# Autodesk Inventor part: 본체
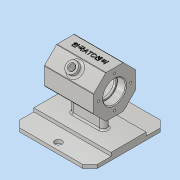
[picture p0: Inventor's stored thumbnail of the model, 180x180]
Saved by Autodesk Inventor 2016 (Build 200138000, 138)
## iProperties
Created: 2018-06
Part Number: 본체
Material: 알루미늄 6061
Document SubType Name: Modeling
Designer: Administrator
Density: 2.7 g/cm^3
Appearance: 알루미늄 - 평지
Mass: 551.991 g
Surface Area: 601.93 cm^2
Volume: 204.441 cm^3
Author: Administrator
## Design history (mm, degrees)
sketch "스케치1"
  geometry: L1 (30, -12.426)-(12.426, -30); L2 (12.426, -30)-(-12.426, -30); L3 (-12.426, -30)-(-30, -12.426); L4 (-30, -12.426)-(-30, 12.426); L5 (-30, 12.426)-(-12.426, 30); L6 (-12.426, 30)-(12.426, 30); L7 (12.426, 30)-(30, 12.426); L8 (30, 12.426)-(30, -12.426); 4 further points
  constraints: 16 end point, 2 coincident, 2 midpoint, 1 horizontal alignment, 1 vertical alignment, 17 other
  dimensions: "d0" = 30 distance of point (30, 0) point (0, 0)
extrude "돌출1" new body sketch "스케치1" stored distance "d1" = 70; taper "d2" = 0 deg
sketch "스케치2"
  geometry: L1 (16, -35)-(16, -23); L2 (16, -23)-(14, -23); L3 (14, -23)-(14, -20); L4 (14, -20)-(25, -20); L5 (25, -20)-(25, 20); L6 (25, 20)-(14, 20); L7 (14, 20)-(14, 23); L8 (14, 23)-(16, 23); L9 (16, 23)-(16, 35); L10 (16, 35)-(0, 35); L11 (0, -35)-(16, -35); 2 further points
  constraints: 22 end point, 8 perpendicular, 2 coincident, 2 horizontal, 2 point on line, 1 vertical, 4 other
  dimensions: "d3" = 70 distance of L10.end L11.start; "d4" = 32 dimension on L1.start; "d5" = 28 dimension on L2.end; "d6" = 50 dimension on L4.end; "d7" = 32 dimension on L8.end; "d8" = 12 distance of L8.end L9.end; "d9" = 40 distance of L4.end L5.end; "d10" = 12 distance of L1.start L1.end; "d11" = 3 distance of L2.end L3.end
revolve "회전1" sketch "스케치2" stored, may be unused: angle "d12" = 90 deg
node "작업 평면1"
sketch "스케치3"
  geometry: L1 (55, 55)-(-55, 55); L2 (-55, 55)-(-55, -55); L3 (-55, -55)-(55, -55); L4 (55, -55)-(55, 55); 3 further points
  constraints: 8 end point, 2 midpoint, 2 parallel, 1 horizontal, 1 horizontal alignment, 1 perpendicular, 1 vertical alignment
  dimensions: "d14" = 110 distance of L3.end L1.start; "d15" = 110 distance of L2.end L3.end
extrude "돌출2" join sketch "스케치3" distance "d16" = 5; taper "d17" = 0 deg
sketch "스케치4"
  geometry: L1 (-25, -55)-(25, -55); L2 (25, -55)-(25, 55); L3 (25, 55)-(-25, 55); L4 (-25, 55)-(-25, -55); 3 further points
  constraints: 8 end point, 2 midpoint, 2 parallel, 1 horizontal, 1 horizontal alignment, 1 perpendicular, 1 vertical alignment
  dimensions: "d18" = 110 distance of L3.end L1.start; "d19" = 50 distance of L2.end L3.end
extrude "돌출3" join sketch "스케치4" distance "d20" = 5; taper "d21" = 0 deg
sketch "스케치5"
  geometry: L1 (-5, -19)-(-5, 19); L2 (5, 19)-(5, -19); A1 r 5 centre (0, 19) between (5, 19) and (-5, 19); A2 r 5 centre (0, -19) between (-5, -19) and (5, -19); 2 further points
  constraints: 4 end point, 4 point on circle, 4 tangent, 2 centre point, 1 horizontal alignment, 1 midpoint, 1 parallel, 1 vertical, 1 vertical alignment
  dimensions: "d22" = 38 distance of L1.start L1.end; "d23" = 5 radius of A1
extrude "돌출4" join sketch "스케치5" stored distance "d24" = 5; taper "d25" = 0 deg
sketch "스케치6"
  geometry: C1 r 8 at (-12.426, 35); 1 further point
  constraints: 1 centre point, 1 coincident
  dimensions: "d26" = 16 diameter of C1
extrude "돌출5" join sketch "스케치6" distance "d27" = 7; taper "d28" = 0 deg
hole "구멍1" diameter "d31" = 8; stored, may be unused: countersink angle "d35" = 90 deg, drill point angle "d37" = 118 deg; dims "d29" = 10, "d30" = 10, "d32" = 6, "d33" = 4, "d34" = 2, "d36" = 30
fillet "모깎기1" dims "d38" = 2
fillet "모깎기2" dims "d39" = 1
fillet "모깎기3" dims "d40" = 0.3
fillet "모깎기4" dims "d41" = 3
fillet "모깎기5" dims "d42" = 3
chamfer "모따기1" distance "d43" = 10; stored, may be unused: second distance "d44" = 2, angle "d45" = 45 deg
sketch "스케치7" dims "d14" = 110, "d15" = 110
  geometry: 3 further points
  constraints: 2 horizontal alignment
  dimensions: "d46" = 45 distance of point (45, 0) point (0, 0); "d47" = 45 distance of point (-45, 0) point (0, 0)
hole "구멍2" sketch "스케치7" at (45, 0), (-45, 0) diameter "d48" = 10; stored, may be unused: countersink angle "d52" = 90 deg, drill point angle "d54" = 118 deg; dims "d49" = 6, "d50" = 4, "d51" = 2, "d53" = 30
sketch "스케치8"
  geometry: L1 (23.946, -59.887)-(23.946, -10.113); L2 (23.946, -10.113)-(0.078, -10.113); L3 (0.078, -10.113)-(0.078, -59.887); L4 (0.078, -59.887)-(23.946, -59.887); 3 further points
  constraints: 2 midpoint, 1 horizontal alignment, 1 vertical alignment, 2 other
feature "엠보싱1" sketch "스케치8" dims "d3" = 70, "d4" = 32, "d5" = 28, "d6" = 50, "d7" = 32, "d8" = 12, "d9" = 40, "d10" = 12, "d11" = 3, "d55" = 0.5, "d56" = 0
sketch "스케치9"
  geometry: 5 further points
  constraints: 1 horizontal alignment, 5 other
  dimensions: "d57" = 23 distance of point (0, 0) point (23, 0); "d60" = 360 deg dimension on point (0, 0) point (23, 0) (derived)
hole "구멍3" sketch "스케치9" at (23, 0), (0, 23), (-23, 0), (0, -23) diameter "d62" = 3.242; stored, may be unused: countersink angle "d66" = 90 deg, drill point angle "d68" = 118 deg; dims "d63" = 8, "d64" = 4, "d65" = 2, "d67" = 10
sketch "스케치10"
  geometry: 5 further points
  constraints: 1 vertical alignment, 5 other
  dimensions: "d69" = 23 distance of point (0, 0) point (0, 23); "d72" = 360 deg dimension on point (0, 0) point (0, 23) (derived)
hole "구멍4" sketch "스케치10" at (0, 23), (-23, 0), (0, -23), (23, 0) diameter "d74" = 3.242; stored, may be unused: countersink angle "d78" = 90 deg, drill point angle "d80" = 118 deg; dims "d75" = 8, "d76" = 4, "d77" = 2, "d79" = 10
chamfer "모따기2" distance "d81" = 1; stored, may be unused: second distance "d82" = 2, angle "d83" = 45 deg
chamfer "모따기3" distance "d84" = 1; stored, may be unused: second distance "d85" = 2, angle "d86" = 45 deg
node "솔리드1"
other parameters: "d13" = -62
